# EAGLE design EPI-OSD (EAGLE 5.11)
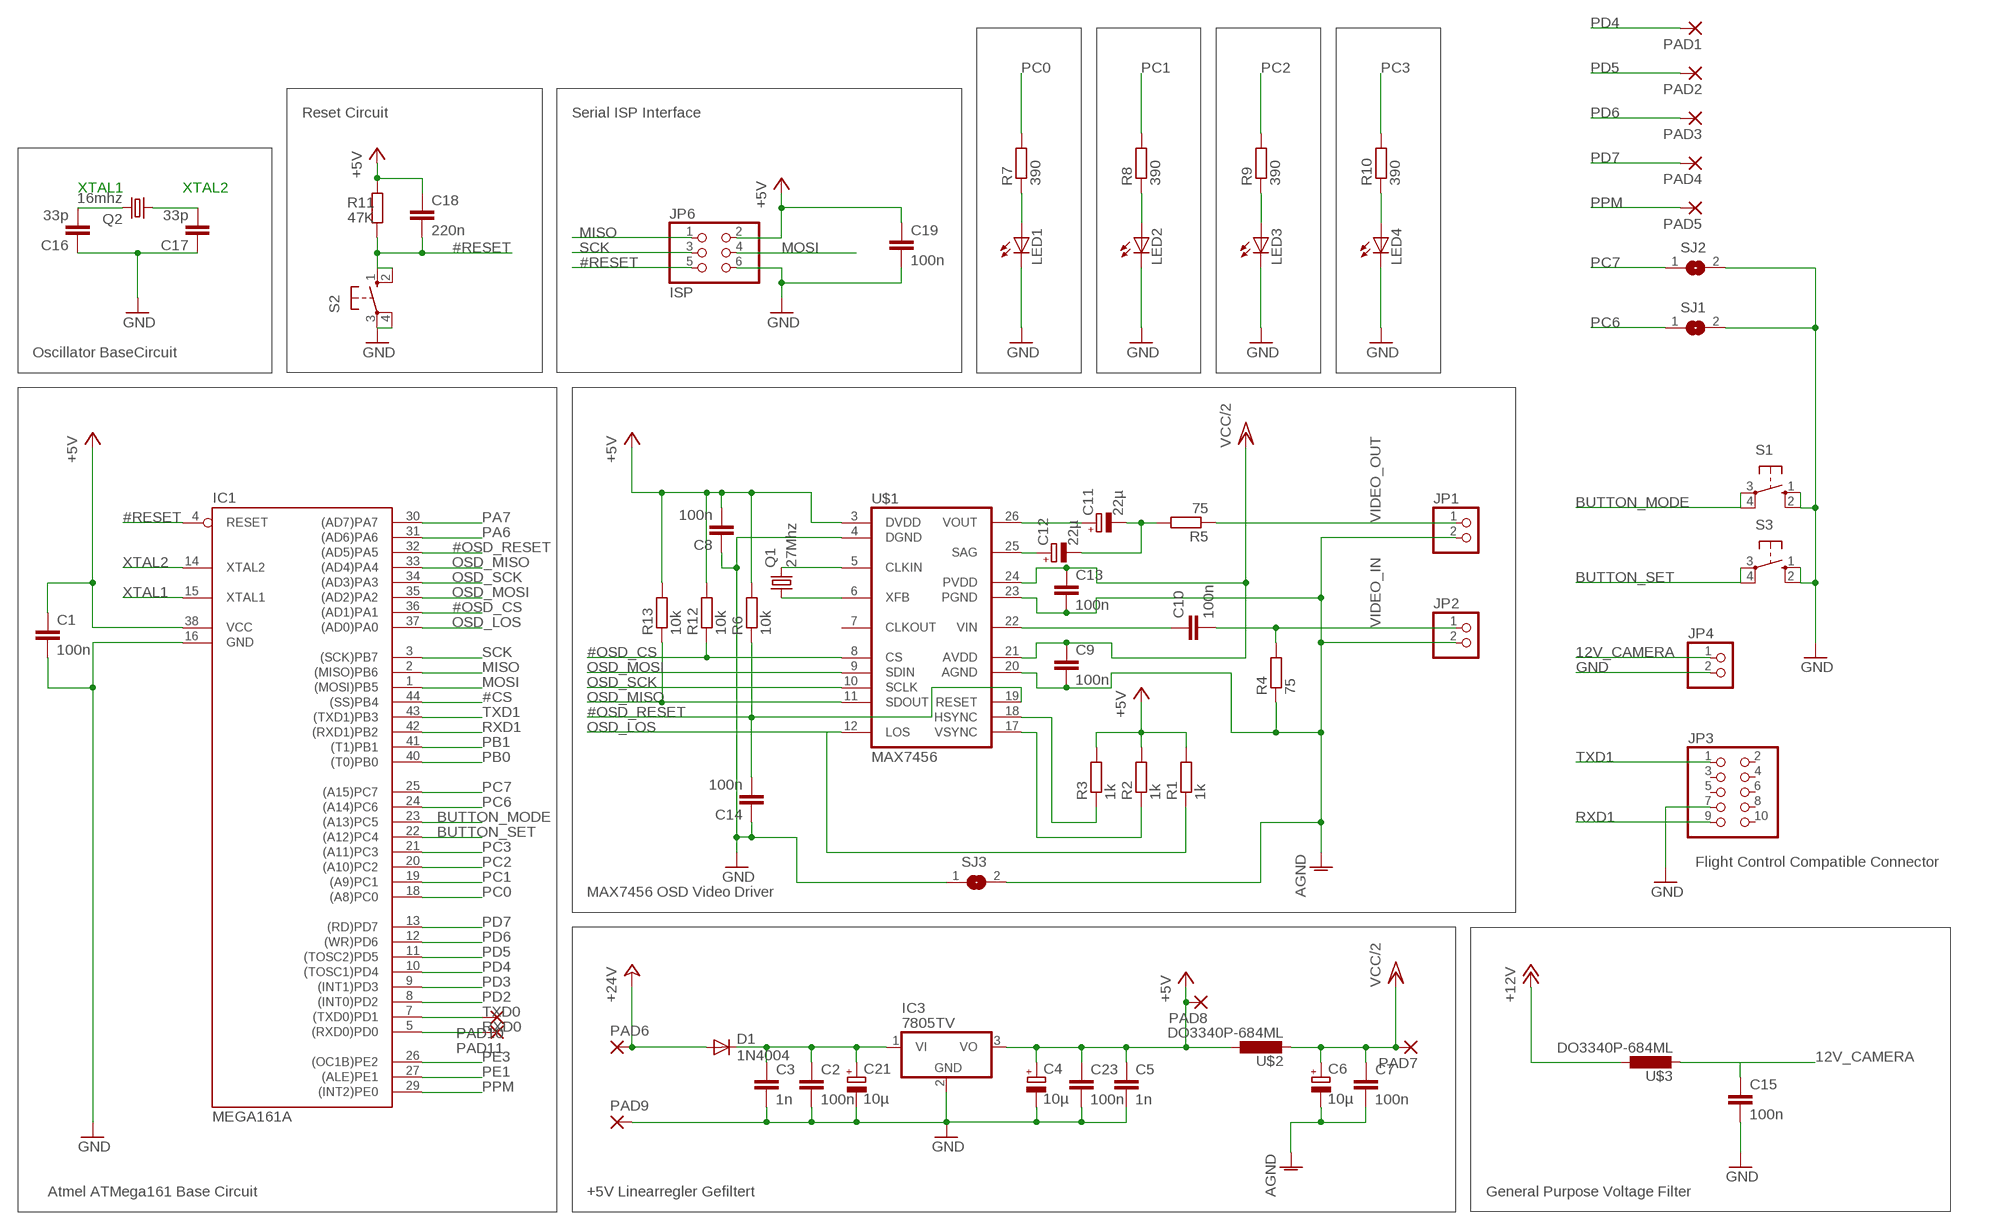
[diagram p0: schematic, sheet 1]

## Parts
C1  100n  C-EUC0603  [C0603]
C2  100n  C-EUC0603  [C0603]
C3  1n  C-EUC0603  [C0603]
C4  10µ  CPOL-EU153CLV-0505  [153CLV-0505]
C5  1n  C-EUC0603  [C0603]
C6  10µ  CPOL-EU153CLV-0505  [153CLV-0505]
C7  100n  C-EUC0603  [C0603]
C8  100n  C-EUC0603  [C0603]
C9  100n  C-EUC0603  [C0603]
C10  100n  C-EUC0603  [C0603]
C11  22µ  CPOL-EU153CLV-0505  [153CLV-0505]
C12  22µ  CPOL-EU153CLV-0505  [153CLV-0505]
C13  100n  C-EUC0603  [C0603]
C14  100n  C-EUC0603  [C0603]
C15  100n  C-EUC0603  [C0603]
C16  33p  C-EUC0603  [C0603]
C17  33p  C-EUC0603  [C0603]
C18  220n  C-EUC0603  [C0603]
C19  100n  C-EUC0603  [C0603]
C21  10µ  CPOL-EU153CLV-0505  [153CLV-0505]
C23  100n  C-EUC0603  [C0603]
D1  1N4004  [DO41-10]
IC1  MEGA161A  [TQFP44]
IC3  7805TV  [TO220V]
JP1  PINHD-1X2/90  [1X02/90]
JP2  PINHD-1X2/90  [1X02/90]
JP3  PINHD-2X5  [2X05]
JP4  PINHD-1X2/90  [1X02/90]
JP6  ISP  PINHD-2X3V  [2X03]
LED1  LEDCHIP-LED0805  [CHIP-LED0805]
LED2  LEDCHIP-LED0805  [CHIP-LED0805]
LED3  LEDCHIP-LED0805  [CHIP-LED0805]
LED4  LEDCHIP-LED0805  [CHIP-LED0805]
PAD1  SMD2  [SMD1,27-2,54]
PAD2  SMD2  [SMD1,27-2,54]
PAD3  SMD2  [SMD1,27-2,54]
PAD4  SMD2  [SMD1,27-2,54]
PAD5  SMD2  [SMD1,27-2,54]
PAD6  WIREPADSMD5-2,5  [5-2,5]
PAD7  SMD2  [SMD1,27-2,54]
PAD8  SMD2  [SMD1,27-2,54]
PAD9  WIREPADSMD5-2,5  [5-2,5]
PAD10  SMD2  [SMD1,27-2,54]
PAD11  SMD2  [SMD1,27-2,54]
Q1  27Mhz  CRYSTALHC49U-V  [HC49U-V@1]
Q2  16mhz  CRYTALHC49S  [HC49/S]
R1  1k  R-EU_R0603  [R0603]
R2  1k  R-EU_R0603  [R0603]
R3  1k  R-EU_R0603  [R0603]
R4  75  R-EU_R0603  [R0603]
R5  75  R-EU_R0603  [R0603]
R6  10k  R-EU_R0603  [R0603]
R7  390  R-EU_R0603  [R0603]
R8  390  R-EU_R0603  [R0603]
R9  390  R-EU_R0603  [R0603]
R10  390  R-EU_R0603  [R0603]
R11  47K  R-EU_R0603  [R0603]
R12  10k  R-EU_R0603  [R0603]
R13  10k  R-EU_R0603  [R0603]
S1  10-XX  [B3F-10XX]
S2  10-XX  [B3F-10XX]
S3  10-XX  [B3F-10XX]
SJ1  SJ  [SJ]
SJ2  SJ  [SJ]
SJ3  SJ  [SJ]
U$1  MAX7456  [TSSOP28]
U$2  DO3340P-684ML  [COILCRAFT_40]
U$3  DO3340P-684ML  [COILCRAFT_40]

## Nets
12V_CAMERA: C15.1 JP4.1 U$3.P$2
#CS: IC1.44((SS)PB4)
#OSD_CS: IC1.36((AD1)PA1) R12.1 U$1.8(CS)
#OSD_RESET: C14.2 IC1.32((AD5)PA5) R6.1 U$1.19(RESET)
#RESET: C18.2 IC1.4(RESET) JP6.5 R11.2 S2.1(S) S2.2(S1)
+5V: C1.1 C4.+ C5.1 C8.2 C18.1 C19.1 C23.1 IC1.38(VCC) IC3.3(VO) JP6.2 PAD8.1(P) R1.2 R2.2 R3.2 R6.2 R11.1 R12.2 R13.2 U$1.3(DVDD) U$2.P$1
+24V: D1.A PAD6.1(P) U$3.P$1 ; supply symbol labelled +12V
AGND: C6.- C7.2 C9.2 C13.2 JP1.2 JP2.2 R4.1 SJ3.2 U$1.20(AGND) U$1.23(PGND)
BUTTON_MODE: IC1.23((A13)PC5) S1.3(P) S1.4(P1)
BUTTON_SET: IC1.22((A12)PC4) S3.3(P) S3.4(P1)
GND: C1.2 C2.2 C3.2 C4.- C5.2 C8.1 C14.1 C15.2 C16.1 C17.1 C19.2 C21.- C23.2 IC1.16(GND) IC3.2(GND) JP3.7 JP4.2 JP6.6 LED1.C LED2.C LED3.C LED4.C PAD9.1(P) S1.1(S) S1.2(S1) S2.3(P) S2.4(P1) S3.1(S) S3.2(S1) SJ1.2 SJ2.2 SJ3.1 U$1.4(DGND)
MISO: IC1.2((MISO)PB6) JP6.1
MOSI: IC1.1((MOSI)PB5) JP6.4
N$1: C2.1 C3.1 C21.+ D1.C IC3.1(VI)
N$2: R3.1 U$1.18(HSYNC)
N$3: R2.1 U$1.17(VSYNC)
N$4: C11.+ U$1.26(VOUT)
N$5: Q1.2 U$1.5(CLKIN)
N$6: Q1.1 U$1.6(XFB)
N$7: C12.+ U$1.25(SAG)
N$8: C11.- C12.- R5.2
N$9: LED1.A R7.1
N$10: C10.1 U$1.22(VIN)
N$11: LED2.A R8.1
N$12: LED3.A R9.1
N$13: LED4.A R10.1
OSD_LOS: IC1.37((AD0)PA0) R1.1 U$1.12(LOS)
OSD_MISO: IC1.33((AD4)PA4) R13.1 U$1.11(SDOUT)
OSD_MOSI: IC1.35((AD2)PA2) U$1.9(SDIN)
OSD_SCK: IC1.34((AD3)PA3) U$1.10(SCLK)
PA6: IC1.31((AD6)PA6)
PA7: IC1.30((AD7)PA7)
PB0: IC1.40((T0)PB0)
PB1: IC1.41((T1)PB1)
PC0: IC1.18((A8)PC0) R7.2
PC1: IC1.19((A9)PC1) R8.2
PC2: IC1.20((A10)PC2) R9.2
PC3: IC1.21((A11)PC3) R10.2
PC6: IC1.24((A14)PC6) SJ1.1
PC7: IC1.25((A15)PC7) SJ2.1
PD2: IC1.8((INT0)PD2)
PD3: IC1.9((INT1)PD3)
PD4: IC1.10((TOSC1)PD4) PAD1.1(P)
PD5: IC1.11((TOSC2)PD5) PAD2.1(P)
PD6: IC1.12((WR)PD6) PAD3.1(P)
PD7: IC1.13((RD)PD7) PAD4.1(P)
PE1: IC1.27((ALE)PE1)
PE3: IC1.26((OC1B)PE2)
PPM: IC1.29((INT2)PE0) PAD5.1(P)
RXD0: IC1.5((RXD0)PD0) PAD11.1(P)
RXD1: IC1.42((RXD1)PB2) JP3.9
SCK: IC1.3((SCK)PB7) JP6.3
TXD0: IC1.7((TXD0)PD1) PAD10.1(P)
TXD1: IC1.43((TXD1)PB3) JP3.1
VCC/2: C6.+ C7.1 C9.1 C13.1 PAD7.1(P) U$1.21(AVDD) U$1.24(PVDD) U$2.P$2
VIDEO_IN: C10.2 JP2.1 R4.2
VIDEO_OUT: JP1.1 R5.1
XTAL1: C16.2 IC1.15(XTAL1) Q2.2
XTAL2: C17.2 IC1.14(XTAL2) Q2.1
Unconnected: IC1.6(NC1) IC1.17(NC2) IC1.28(NC3) IC1.39(NC4) JP3.2 JP3.3 JP3.4 JP3.5 JP3.6 JP3.8 JP3.10 U$1.7(CLKOUT)

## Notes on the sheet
- Reset Circuit | Serial ISP Interface
- Oscillator BaseCircuit
- Flight Control Compatible Connector
- MAX7456 OSD Video Driver
- Atmel ATMega161 Base Circuit | +5V Linearregler Gefiltert | General Purpose Voltage Filter

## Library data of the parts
C1-C3 C5 C7-C10 C13-C19 C23 = rcl:C-EU: CAPACITOR, European symbol
C4 C6 C11 C12 C21 = rcl:CPOL-EU: POLARIZED CAPACITOR, European symbol
D1 = diode:1N4004: DIODE
IC1 = atmel:MEGA161*: MICROCONTROLLER 16 Kbytes FLASH 512 bytes EEPROM 1 Kbytes SRAM dual UART hardware multiplier Source: avr.lbr; MPN: ATMEGA16-16AU; OC_FARNELL: 9171134; OC_NEWARK: 96K6515
IC3 = linear:78*: Positive VOLTAGE REGULATOR Source: http://cache.national.com/ds/LM/LM78L05.pdf http://www.fairchildsemi.com/ds/LM/LM7805.pdf
JP1 JP2 JP4 = pinhead:PINHD-1X2: PIN HEADER
JP3 = pinhead:PINHD-2X5: PIN HEADER
JP6 = pinhead:PINHD-2X3: PIN HEADER
LED1-LED4 = led:LED: LED
PAD1-PAD5 PAD7 PAD8 PAD10 PAD11 = wirepad:SMD2: SMD PAD
PAD6 PAD9 = wirepad:WIREPAD: Wire PAD connect wire on PCB
Q1 = crystal:CRYSTAL: CRYSTAL; OC_FARNELL: 1666969; OC_NEWARK: unknown
Q2 = crystal:CRYTAL: CRYSTAL
R1-R13 = rcl:R-EU_: RESISTOR, European symbol
S1-S3 = switch-omron:10-XX: OMRON SWITCH
SJ1-SJ3 = jumper:SJ: SMD solder JUMPER
U$1 = max7456:MAX7456
U$2 U$3 = rcl-2:DO3340P-684ML

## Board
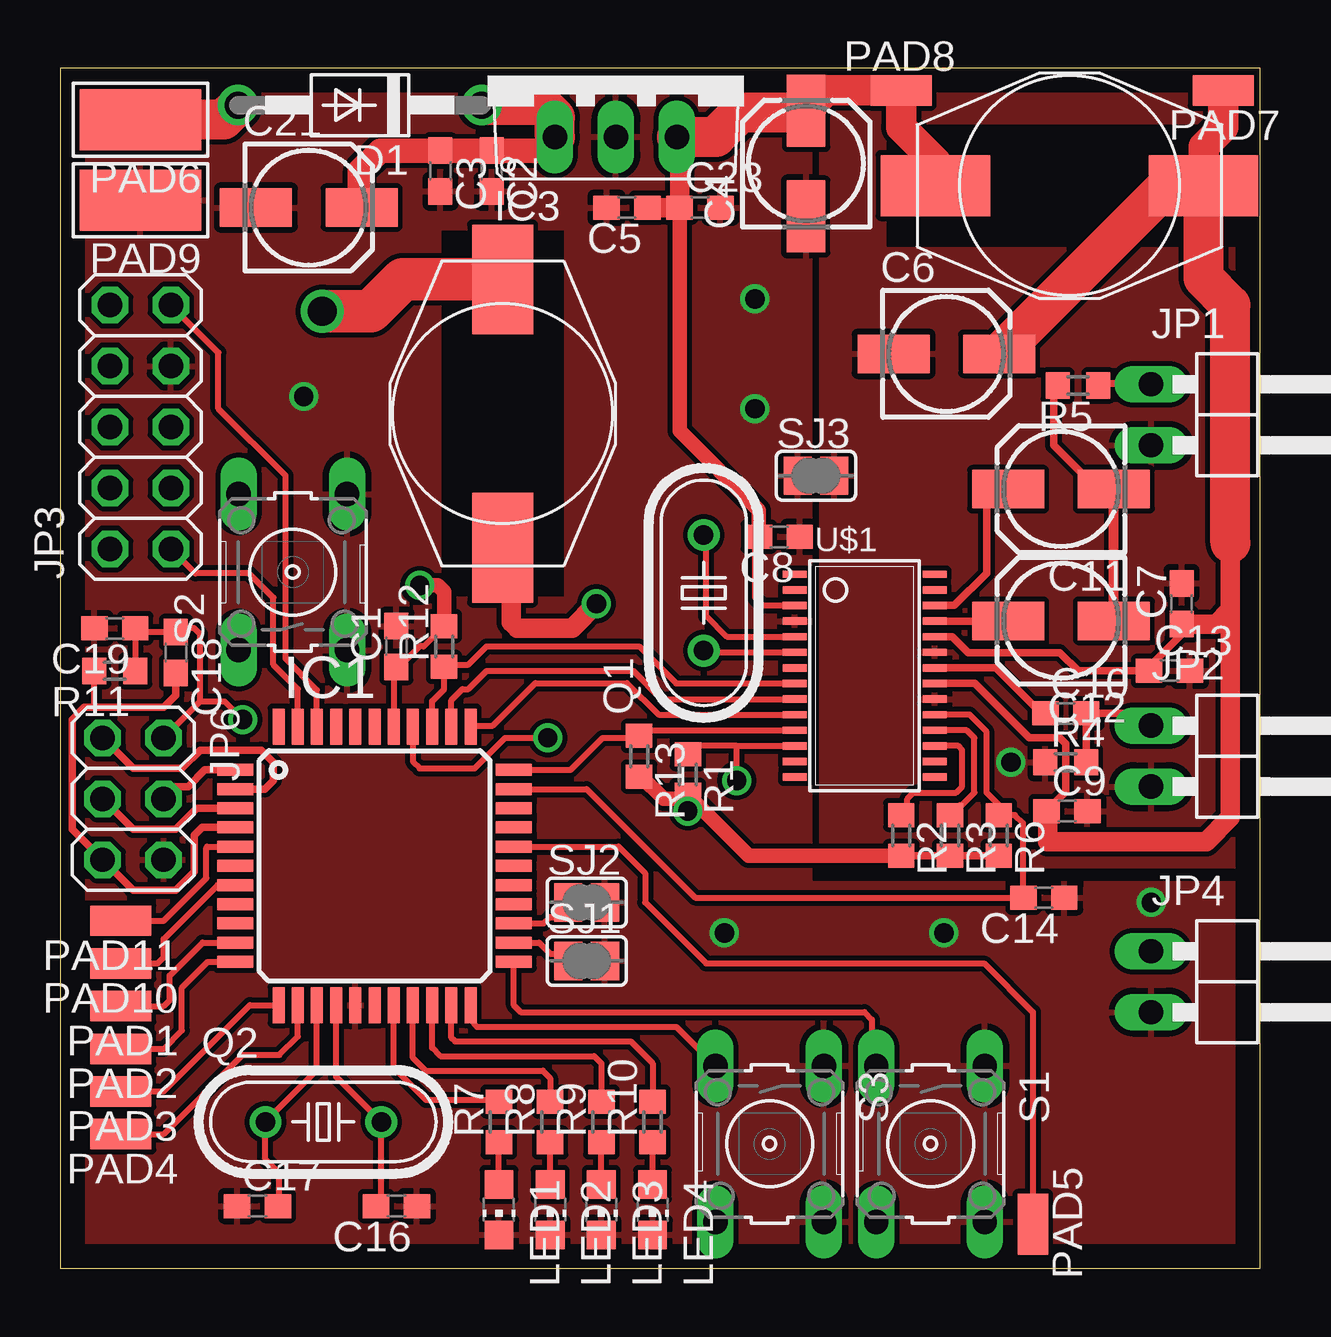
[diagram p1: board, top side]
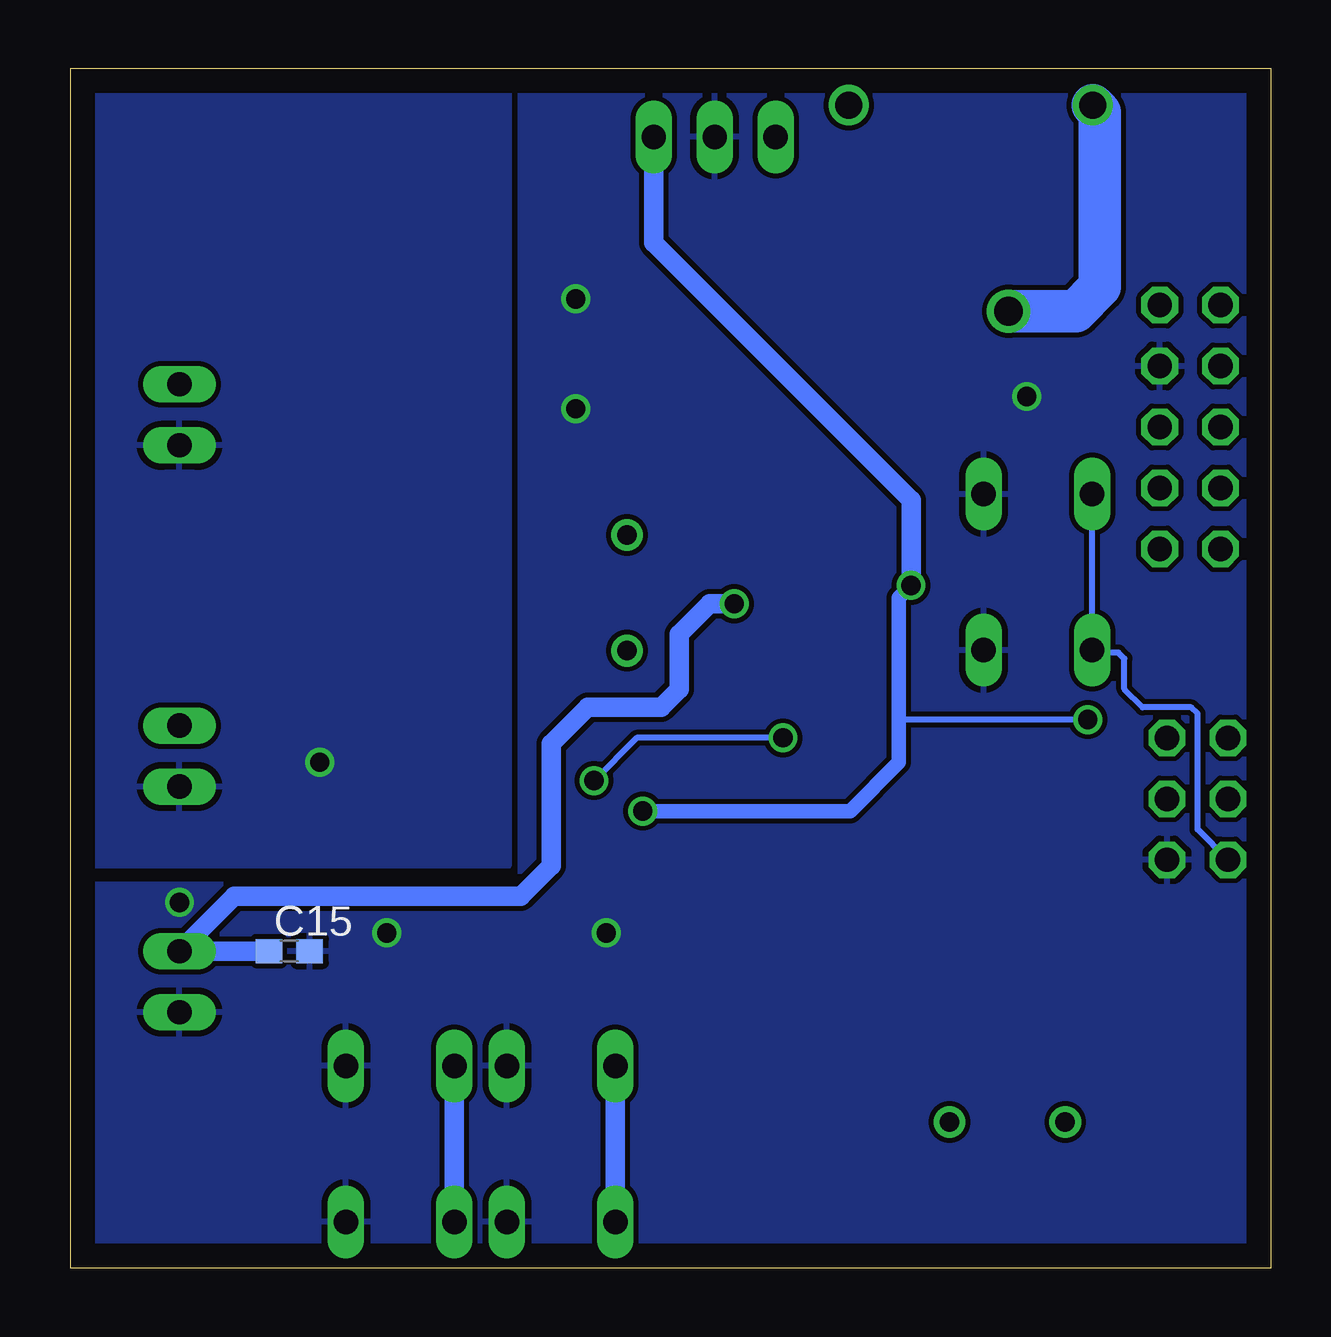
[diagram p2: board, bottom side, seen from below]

Size 50 x 50 mm. Coordinates in mm from the lower left corner, seen from the top.
Outline: 0,0 50,0 50,50 0,50 0,0
Copper layers (1*16): Top 0.035mm / dielectric 1.5mm / Bottom 0.035mm
Design rules "default": minimum track width 12mil, minimum drill 0.8mm, track to track 8mil, track to pad 8mil, pad to pad 8mil, via to via 8mil, smd to smd 8mil, copper to edge 40mil, drill to drill 8mil, minimum pad ring 10mil, minimum via ring 8mil, stop-mask expansion 4mil, vias tented up to drill 0mil, thermal gap 10mil

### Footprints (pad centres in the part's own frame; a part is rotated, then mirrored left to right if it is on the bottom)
C0603 = smd 1.1 x 1: 1 -0.85,0; 2 0.85,0
153CLV-0505 = smd 3 x 1.6: + 2.2,0; - -2.2,0
DO41-10 = drill 1.118 round: A 5.08,0; C -5.08,0
TQFP44 = smd 1.5 x 0.5: 1 -5.8,4; 2 -5.8,3.2; 3 -5.8,2.4; 4 -5.8,1.6; 5 -5.8,0.8; 6 -5.8,0; 7 -5.8,-0.8; 8 -5.8,-1.6; 9 -5.8,-2.4; 10 -5.8,-3.2; 11 -5.8,-4; 23 5.8,-4; 24 5.8,-3.2; 25 5.8,-2.4; 26 5.8,-1.6; 27 5.8,-0.8; 28 5.8,0; 29 5.8,0.8; 30 5.8,1.6; 31 5.8,2.4; 32 5.8,3.2; 33 5.8,4 | smd 0.5 x 1.5: 12 -4,-5.8; 13 -3.2,-5.8; 14 -2.4,-5.8; 15 -1.6,-5.8; 16 -0.8,-5.8; 17 0,-5.8; 18 0.8,-5.8; 19 1.6,-5.8; 20 2.4,-5.8; 21 3.2,-5.8; 22 4,-5.8; 34 4,5.8; 35 3.2,5.8; 36 2.4,5.8; 37 1.6,5.8; 38 0.8,5.8; 39 0,5.8; 40 -0.8,5.8; 41 -1.6,5.8; 42 -2.4,5.8; 43 -3.2,5.8; 44 -4,5.8
TO220V = drill 1.016 long: 1 -2.54,-2.54; 2 0,-2.54; 3 2.54,-2.54
1X02/90 = drill 1.016 long: 1 -1.27,-3.81; 2 1.27,-3.81
2X05 = drill 1.016 octagon: 1 -5.08,-1.27; 2 -5.08,1.27; 3 -2.54,-1.27; 4 -2.54,1.27; 5 0,-1.27; 6 0,1.27; 7 2.54,-1.27; 8 2.54,1.27; 9 5.08,-1.27; 10 5.08,1.27
2X03 = drill 1.016 octagon: 1 -2.54,-1.27; 2 -2.54,1.27; 3 0,-1.27; 4 0,1.27; 5 2.54,-1.27; 6 2.54,1.27
CHIP-LED0805 = smd 1.2 x 1.2: A 0,-1.05; C 0,1.05
SMD1,27-2,54 = smd 1.27 x 2.54: 1 0,0
5-2,5 = smd 2.54 x 5.08: 1 0,0
HC49U-V@1 = drill 0.813 round: 1 -2.413,0; 2 2.413,0
HC49/S = drill 0.813 round: 1 -2.413,0; 2 2.413,0
R0603 = smd 1 x 1.1: 1 -0.85,0; 2 0.85,0
B3F-10XX = drill 1.016 long: 1 -3.251,2.261; 2 3.251,2.261; 3 -3.251,-2.261; 4 3.251,-2.261
SJ = smd 1.168 x 1.6: 1 -0.762,0; 2 0.762,0
TSSOP28 = smd 0.305 x 0.991: 1 -4.225,-2.918; 2 -3.575,-2.918; 3 -2.925,-2.918; 4 -2.275,-2.918; 5 -1.625,-2.918; 6 -0.975,-2.918; 7 -0.325,-2.918; 8 0.325,-2.918; 9 0.975,-2.918; 10 1.625,-2.918; 11 2.275,-2.918; 12 2.925,-2.918; 13 3.575,-2.918; 14 4.225,-2.918; 15 4.225,2.918; 16 3.575,2.918; 17 2.925,2.918; 18 2.275,2.918; 19 1.625,2.918; 20 0.975,2.918; 21 0.325,2.918; 22 -0.325,2.918; 23 -0.975,2.918; 24 -1.625,2.918; 25 -2.275,2.918; 26 -2.925,2.918; 27 -3.575,2.918; 28 -4.225,2.918
COILCRAFT_40 = smd 4.572 x 2.54: P$1 -5.588,0; P$2 5.588,0

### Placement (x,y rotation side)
C1  14.02,25.91 90 top
C2  17.98,45.72 270 top
C3  15.85,45.72 270 top
C4  31.09,46.02 90 top
C5  23.62,44.2 180 top
C6  36.93,38.1 0 top
C7  46.74,27.69 90 top
C8  29.97,30.48 180 top
C9  41.96,19.05 0 top
C10  41.91,23.11 0 top
C11  41.71,32.46 180 top
C12  41.71,26.97 180 top
C13  46.23,24.89 0 top
C14  41,15.44 180 top
C15  40.89,13.21 0 bottom
C16  14.02,2.59 180 top
C17  8.23,2.59 0 top
C18  4.83,25.65 270 top
C19  2.29,26.67 180 top
C21  10.36,44.2 0 top
C23  26.67,44.2 0 top
D1  12.5,48.46 180 top
IC1  13.11,16.76 0 top
IC3  23.16,49.68 0 top
JP1  49.28,35.56 270 top
JP2  49.28,21.34 270 top
JP3  3.35,35.05 90 top
JP4  49.28,11.94 270 top
JP6  3.05,19.56 270 top
LED1  18.29,2.44 180 top
LED2  20.42,2.44 180 top
LED3  22.56,2.44 180 top
LED4  24.69,2.44 180 top
PAD1  2.54,10.92 90 top
PAD2  2.54,9.14 90 top
PAD3  2.54,7.37 90 top
PAD4  2.54,5.59 90 top
PAD5  40.54,1.83 180 top
PAD6  3.35,47.85 90 top
PAD7  48.46,49.07 90 top
PAD8  35.05,49.07 270 top
PAD9  3.35,44.5 90 top
PAD10  2.54,12.7 90 top
PAD11  2.54,14.48 90 top
Q1  26.82,28.14 90 top
Q2  10.97,6.1 0 top
R1  26.16,20.57 270 top
R2  35.05,18.03 270 top
R3  37.08,18.03 270 top
R4  41.91,21.08 0 top
R5  42.42,36.78 180 top
R6  39.12,18.03 270 top
R7  18.29,6.1 90 top
R8  20.42,6.1 90 top
R9  22.56,6.1 90 top
R10  24.69,6.1 90 top
R11  2.29,24.89 180 top
R12  16,25.91 90 top
R13  24.13,21.34 270 top
S1  36.27,5.18 270 top
S2  9.7,29.01 90 top
S3  29.57,5.18 270 top
SJ1  21.95,12.8 0 top
SJ2  21.95,15.24 0 top
SJ3  31.5,33.02 0 top
U$1  33.53,24.69 270 top
U$2  42.06,45.11 0 top
U$3  18.44,35.61 270 top

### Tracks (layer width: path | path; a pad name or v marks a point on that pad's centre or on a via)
12V_CAMERA  (via drill 0.8 pad 1.02)
  Top 0.61: 18.96,29.63 18.8,29.46 18.8,29.67 U$3.P$2
  Top 0.813: 18.8,29.67 18.8,26.92 19.05,26.67 21.34,26.67 v22.35,27.69
  Bottom 0.813: v22.35,27.69 23.37,27.69 24.64,26.42 24.64,24.13 25.4,23.37 28.45,23.37 29.97,21.84 29.97,16.76 31.24,15.49 43.18,15.49 JP4.1 C15.1
#OSD_CS
  Top 0.254: IC1.36 15.51,23.63 16,24.13 R12.1 16.09,25.15 17.02,25.15 17.78,25.91 24.13,25.91 25.67,24.36 U$1.8
#OSD_RESET
  Top 0.254: U$1.19 37.9,23.06 38.61,22.35 38.61,19.81 39.12,19.3 R6.1 39.79,18.88 40.13,18.54 40.13,15.46 C14.2 26.47,15.44 21.95,19.96 IC1.32
#RESET
  Top 0.254: R11.2 1.44,23.46 1.52,23.37
  Top 0.305: IC1.4 5.92,18.36 5.59,18.03 5.59,16.51 4.83,15.75 3.05,15.75 JP6.5 0.51,18.29 0.51,22.86 1.02,23.37 1.52,23.37 4.32,23.37 4.83,23.88 C18.2
  Bottom 0.254: JP6.5 3.05,18.29 3.05,23.11 3.3,23.37 5.33,23.37 6.1,24.13 6.1,25.4 6.35,25.65 7.34,25.65 S2.1 S2.2
+5V  (via drill 0.8 pad 1.02)
  Top 0.254: R11.1 C19.1 3.3,26.5 C18.1 4.99,26.67 5.59,26.67 5.84,26.42 5.84,23.62 | JP6.2 5.84,23.62 | IC1.38 13.91,24.94 C1.1 14.14,25.06 14.99,25.91 15.15,25.91 R12.2 | 24.22,20.49 R13.2 | R1.2 26,19.56 | U$1.3 29.28,27.61 28.96,27.94 28.96,30.31 C8.2 | 5.84,23.62 6.86,23.62 v7.62,22.86
  Top 0.305: R6.2 R3.2 R2.2
  Top 0.61: 24.22,20.49 25.15,19.56 26,19.56 | R2.2 28.7,17.18 R1.2 v26.16,19.05 | C23.1 25.82,34.89 29.12,31.58 C8.2 | v14.99,28.45 15.75,28.45 16,28.19 R12.2
  Top 0.813: IC3.3 25.82,47.03 C23.1 C5.1
  Top 1.27: C4.+ 31.94,49.07 PAD8.1 35.05,47.55 36.47,46.13 U$2.P$1
  Top 1.676: IC3.3 27.33,47.14 28.35,48.16 31.02,48.16 C4.+
  Bottom 0.254: v7.62,22.86 15.49,22.86
  Bottom 0.61: v26.16,19.05 17.53,19.05 15.49,21.08 15.49,22.86 15.49,27.94 v14.99,28.45
  Bottom 0.813: v14.99,28.45 14.99,32 25.7,42.72 IC3.3
+24V  (via drill 1.2 pad 1.02)
  Top 1.676: PAD6.1 6.81,47.85 D1.A
  Top 1.778: U$3.P$1 14.28,41.2 12.95,39.88 v10.92,39.88
  Bottom 1.778: v10.92,39.88 8.13,39.88 7.11,40.89 7.11,48.16 D1.A
AGND  (via drill 0.8 pad 1.02)
  other vias: 39.62,21.08
  pour Top: 31.75,50.04 50.04,50.04 50.04,16.76 31.75,16.76
  pour Bottom: 31.75,50.04 31.75,16.76 50.04,16.76 50.04,50.04
BUTTON_MODE
  Top 0.254: IC1.23 18.91,10.96 19.2,10.67 33.53,10.67 33.83,10.36 33.83,8.61 S1.3
  Bottom 0.813: S1.3 S1.4
BUTTON_SET
  Top 0.254: IC1.22 17.11,10.33 17.37,10.06 25.68,10.06 S3.3
  Bottom 0.813: S3.3 S3.4
GND  (via drill 0.8 pad 1.02)
  other vias: 27.69,13.97 28.96,40.39 28.96,35.81 10.16,36.32 36.83,13.97 45.47,15.24
  pour Top: 0,0 31.24,0 31.24,50.04 0,50.04
  pour Top: 30.99,0 50.04,0 50.04,16 30.99,16
  pour Bottom: 0,0 50.04,0 50.04,16 31.24,16 31.24,50.04 0,50.04
MISO
  Top 0.305: IC1.2 8.53,19.96 8.89,20.32 8.89,21.08 8.38,21.59 5.84,21.59 5.08,20.83 3.05,20.83 JP6.1
MOSI
  Top 0.305: IC1.1 6.03,20.76 5.33,20.07 4.83,20.07 JP6.4
N$1
  Top 1.016: IC3.1 20.05,46.57 C2.1 C3.1 13.35,46.57 12.5,45.72 12.5,44.26 C21.+
  Top 1.676: D1.C 20.12,48.46 20.62,47.95 IC3.1
N$2
  Top 0.254: U$1.18 37.78,22.41 38.1,22.1 38.1,19.81 37.59,19.3 37.5,19.3 R3.1
N$3
  Top 0.254: U$1.17 37.42,21.76 37.59,21.59 37.59,20.07 37.34,19.81 35.56,19.81 35.31,19.56 35.31,19.14 R2.1
N$4
  Top 0.254: 38.61,32.32 C11.+
  Top 0.305: U$1.26 37.27,27.61 38.61,28.96 38.61,32.32
N$5
  Top 0.254: U$1.5 27.79,26.31 26.92,27.18 26.92,30.45 Q1.2
N$6
  Top 0.254: U$1.6 26.89,25.66 Q1.1
N$7
  Top 0.254: 39.26,26.96 C12.+
  Top 0.305: U$1.25 39.26,26.96
N$8
  Top 0.254: C11.- 43.23,32.46 | 41.4,36.61 R5.2
  Top 0.305: 43.23,32.46 41.4,34.29 41.4,36.61
  Top 0.406: C12.- C11.-
N$9
  Top 0.254: LED1.A R7.1
N$10
  Top 0.305: U$1.22 38.99,25.01 40.64,23.37 40.81,23.37 C10.1
N$11
  Top 0.254: LED2.A R8.1
N$12
  Top 0.254: LED3.A R9.1
N$13
  Top 0.254: LED4.A R10.1
OSD_LOS  (via drill 0.8 pad 1.02)
  Top 0.254: 28.19,21.76 26.5,21.76 R1.1 | 28.19,21.76 U$1.12 | IC1.37 14.71,21.11 14.99,20.83 17.27,20.83 18.54,22.1 v20.32,22.1 | v28.19,20.32 28.19,21.76
  Bottom 0.254: v20.32,22.1 26.42,22.1 v28.19,20.32
OSD_MISO
  Top 0.254: U$1.11 24.36,22.41 R13.1 24.04,22.1 22.61,22.1 21.27,20.76 IC1.33
OSD_MOSI
  Top 0.254: U$1.9 25.05,23.71 23.88,24.89 17.78,24.89 17.02,24.13 16.76,24.13 16.31,23.67 IC1.35
OSD_SCK
  Top 0.254: U$1.10 24.94,23.06 23.62,24.38 19.81,24.38 18.03,22.61 17.15,22.61 IC1.34
PC0
  Top 0.254: IC1.18 13.91,8.34 15.24,7.01 18.22,7.01 R7.2
PC1
  Top 0.254: IC1.19 14.71,8.76 15.24,8.23 20.12,8.23 20.42,7.92 R8.2
PC2
  Top 0.254: IC1.20 15.51,9.18 15.85,8.84 22.25,8.84 22.55,8.53 R9.2
PC3
  Top 0.254: IC1.21 16.31,9.6 16.46,9.45 23.77,9.45 24.69,8.53 R10.2
PC6
  Top 0.254: IC1.24 19.96,13.56 20.42,13.11 20.88,13.11 SJ1.1
PC7
  Top 0.254: IC1.25 20.16,14.36 20.42,14.63 20.57,14.63 SJ2.1
PD4
  Top 0.254: IC1.10 5.94,13.56 4.57,12.19 4.57,11.18 4.32,10.92 PAD1.1
PD5
  Top 0.254: IC1.11 6.16,12.76 5.08,11.68 5.08,9.91 4.32,9.14 PAD2.1
PD6
  Top 0.254: IC1.12 7.92,10.96 4.32,7.37 PAD3.1
PD7
  Top 0.254: IC1.13 9.91,9.65 9.14,8.89 7.62,8.89 4.32,5.59 PAD4.1
PPM
  Top 0.254: IC1.29 23.28,17.56 24.38,16.46 24.38,15.24 26.92,12.7 38.51,12.7 40.54,10.67 PAD5.1
RXD0
  Top 0.254: IC1.5 6.13,17.56 6.1,17.53 6.1,16.26 4.32,14.48 PAD11.1
RXD1
  Top 0.254: IC1.42 10.71,24.09 9.4,25.4 9.4,33.02 6.6,35.81 6.6,38.15 JP3.9
SCK
  Top 0.305: IC1.3 5.7,19.16 4.83,18.29 3.05,18.29 JP6.3
TXD0
  Top 0.254: IC1.7 6.57,15.96 4.32,13.72 4.32,12.95 4.06,12.7 PAD10.1
TXD1
  Top 0.254: IC1.43 9.91,24.13 8.89,25.15 8.89,27.94 7.87,28.96 5.64,28.96 JP3.1
VCC/2
  Top 0.305: U$1.24 37.19,26.31 37.85,25.65 41.66,25.65 42.42,24.89 C13.1 45.38,25.06 46.74,26.42 C7.1 | U$1.21 38.12,24.36 40.39,22.1 41.66,22.1 41.91,21.84 41.91,19.85 C9.1
  Top 0.813: 48.77,27.43 48.77,30.23 | C7.1 48.17,26.84 48.77,27.43 | 48.77,27.43 48.77,18.8 47.75,17.78 41.15,17.78 41.15,19.01 C9.1
  Top 1.27: U$2.P$2 47.65,46.74 48.46,47.55 PAD7.1
  Top 1.676: C6.+ 46.14,45.11 U$2.P$2 47.65,41.25 48.77,40.13 48.77,30.23
VIDEO_IN
  Top 0.305: JP2.1 45.01,23.11 C10.2 R4.2
VIDEO_OUT
  Top 0.254: 43.37,36.88 R5.1
  Top 0.305: JP1.1 43.37,36.88
XTAL1
  Top 0.254: IC1.15 11.51,7.97 Q2.2 13.39,2.55 C16.2
XTAL2
  Top 0.254: IC1.14 10.71,8.24 Q2.1 8.56,4.55 9.14,3.96 9.14,2.65 C17.2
